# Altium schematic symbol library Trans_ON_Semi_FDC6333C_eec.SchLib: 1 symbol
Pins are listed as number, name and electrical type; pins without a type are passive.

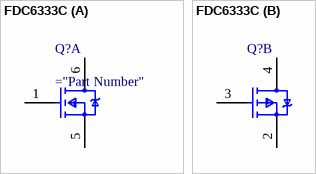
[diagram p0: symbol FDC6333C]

## FDC6333C
designator Q?  (value not drawn)
part A pins: 1 1 G, 5 1 S, 6 1 D
part B pins: 2 2 S, 3 2 G, 4 2 D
